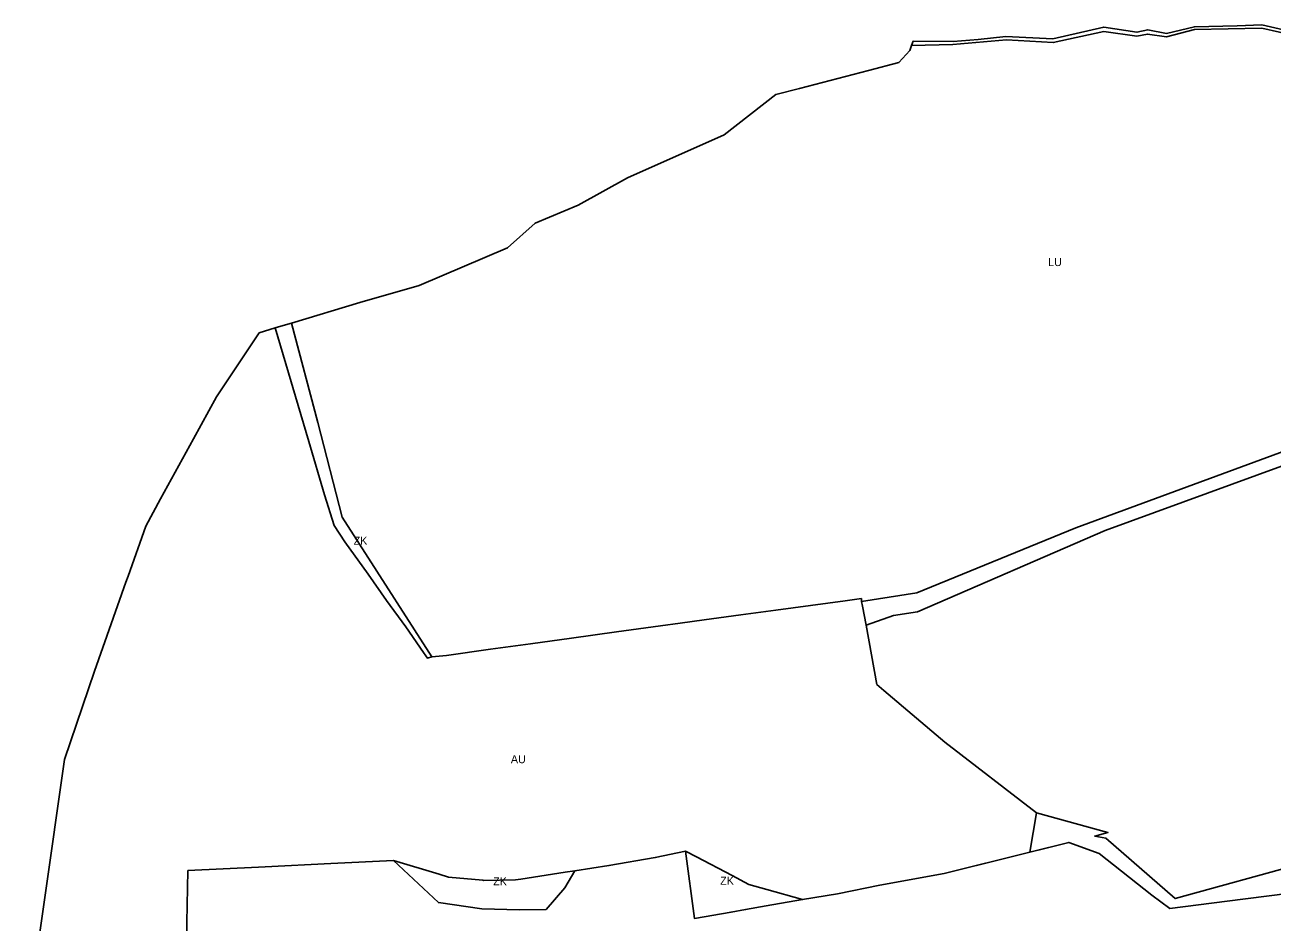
# Model space of a CAD drawing. Extents: x -521261 to -517465, y -1182764 to -1179456.
# Drawn here: x -521236 to -520457, y -1180873 to -1180313 of the extents above; entities that cross this region are included whole.
import ezdxf

# ---------------------------------------------------------------- set-up
doc = ezdxf.new("R2010")
doc.units = 0
for name, color, linetype in [('90640013', 7, 'Continuous'), ('90710013', 7, 'Continuous'), ('90750013', 7, 'Continuous'), ('90770013', 7, 'Continuous')]:
    doc.layers.add(name, color=color, linetype=linetype)

msp = doc.modelspace()

# ---------------------------------------------------------------- linework, layer by layer
at = {"layer": '90640013'}
msp.add_lwpolyline([(-520430.53, -1180322.01), (-520463.59, -1180314.64), (-520505.71, -1180315.43), (-520523.12, -1180320.04), (-520535.11, -1180318.28), (-520541.7, -1180319.56), (-520562.36, -1180316.64), (-520593.96, -1180323.61), (-520623.24, -1180321.76), (-520656.71, -1180324.81), (-520682.5, -1180325.44), (-520681.46, -1180322.66), (-520656.46, -1180322.89), (-520640.91, -1180321.65), (-520623.67, -1180319.82), (-520594.16, -1180321.19), (-520562.44, -1180313.88), (-520541.65, -1180317.16), (-520534.97, -1180315.56), (-520523.11, -1180317.8), (-520505.74, -1180313.71), (-520478.98, -1180313.03), (-520463.57, -1180312.56), (-520429.19, -1180320.47)], dxfattribs=at)
at = {"layer": '90710013'}
for points in [[(-520982.12, -1180707.29), (-520984.95, -1180708.02), (-520985.98, -1180706.63), (-520987.41, -1180704.59), (-520998.52, -1180688.54), (-521010.53, -1180672.06), (-521022.04, -1180655.73), (-521036.66, -1180635.53), (-521043.32, -1180625.33), (-521049.31, -1180606.17), (-521059.04, -1180572.8), (-521080, -1180501.82), (-521076.54, -1180500.79), (-521069.84, -1180498.79), (-521053.35, -1180560.82), (-521038.23, -1180619.96), (-521027.44, -1180636.91)], [(-520772.933, -1180852.547), (-520750.61, -1180858.87), (-520773.26, -1180862.77), (-520786.22, -1180865.2), (-520795.24, -1180866.73), (-520818.13, -1180870.65), (-520823.65, -1180828.61), (-520816.859, -1180832.176), (-520794.487, -1180843.925), (-520784.08, -1180849.39)], [(-520898.888, -1180841.868), (-520892.8, -1180840.93), (-520899.15, -1180851.67), (-520910.87, -1180865.15), (-520927.48, -1180865.42), (-520950.88, -1180864.7), (-520978.13, -1180860.76), (-521006.09, -1180834.57), (-520977.554, -1180843.132), (-520971.86, -1180844.84), (-520950.267, -1180846.845), (-520949.78, -1180846.89), (-520929.98, -1180846.66), (-520926.691, -1180846.153)]]:
    msp.add_lwpolyline(points, close=True, dxfattribs=at)
for points in [[(-520418.21, -1180576.2), (-520561.44, -1180628.41), (-520678.77, -1180679.14), (-520693.72, -1180681.5), (-520710.85, -1180687.4), (-520713.2, -1180675.69), (-520713.69, -1180672.62), (-520679.15, -1180667.26), (-520579.89, -1180626.79), (-520418.64, -1180567.25)], [(-520447.63, -1180855.08), (-520485.24, -1180860), (-520521.14, -1180864.38), (-520532.28, -1180856.24), (-520565.24, -1180830.11), (-520584.27, -1180823.22), (-520608.5, -1180829.229), (-520604.38, -1180804.7), (-520559.81, -1180816.94), (-520567.99, -1180819.26), (-520561.06, -1180820.59), (-520517.73, -1180858.28), (-520437.72, -1180836.09)]]:
    msp.add_lwpolyline(points, dxfattribs=at)
at = {"layer": '90750013'}
msp.add_lwpolyline([(-521236.44, -1180945.21), (-521211.68, -1180771.41), (-521193.04, -1180716.3), (-521173.37, -1180660.62), (-521171.97, -1180656.94), (-521160.99, -1180625.55), (-521151.7, -1180608.67), (-521131.22, -1180571.13), (-521116.74, -1180544.81), (-521090.08, -1180504.84), (-521080, -1180501.82), (-521059.04, -1180572.8), (-521049.31, -1180606.17), (-521043.32, -1180625.33), (-521036.66, -1180635.53), (-521022.04, -1180655.73), (-521010.53, -1180672.06), (-520998.52, -1180688.54), (-520987.41, -1180704.59), (-520985.98, -1180706.63), (-520984.95, -1180708.02), (-520982.12, -1180707.29), (-520972.99, -1180706.39), (-520945.52, -1180702.45), (-520920.54, -1180699.08), (-520894.99, -1180695.67), (-520866.85, -1180691.76), (-520839.32, -1180687.91), (-520826.97, -1180686.18), (-520811.97, -1180684.15), (-520789.12, -1180681.02), (-520767.28, -1180678.06), (-520745.61, -1180675.16), (-520724.02, -1180672.26), (-520713.87, -1180670.87), (-520713.69, -1180672.62), (-520713.2, -1180675.69), (-520710.85, -1180687.4), (-520704.09, -1180724.52), (-520699.81, -1180728.35), (-520661.61, -1180760.58), (-520604.38, -1180804.7), (-520608.5, -1180829.229), (-520662.13, -1180842.53), (-520702.34, -1180849.97), (-520728.86, -1180855.3), (-520750.61, -1180858.87), (-520772.933, -1180852.547), (-520784.08, -1180849.39), (-520794.487, -1180843.925), (-520816.859, -1180832.176), (-520823.65, -1180828.61), (-520842.59, -1180832.65), (-520871.59, -1180837.65), (-520892.8, -1180840.93), (-520898.888, -1180841.868), (-520926.691, -1180846.153), (-520929.98, -1180846.66), (-520949.78, -1180846.89), (-520950.267, -1180846.845), (-520971.86, -1180844.84), (-520977.554, -1180843.132), (-521006.09, -1180834.57), (-521045.3, -1180836.39), (-521086.39, -1180838.41), (-521090.43, -1180838.7), (-521134.59, -1180840.77), (-521135.49, -1180884)], dxfattribs=at)
at = {"layer": '90770013'}
for points in [[(-520418.64, -1180567.25), (-520579.89, -1180626.79), (-520679.15, -1180667.26), (-520713.69, -1180672.62), (-520713.87, -1180670.87), (-520724.02, -1180672.26), (-520745.61, -1180675.16), (-520767.28, -1180678.06), (-520789.12, -1180681.02), (-520811.97, -1180684.15), (-520826.97, -1180686.18), (-520839.32, -1180687.91), (-520866.85, -1180691.76), (-520894.99, -1180695.67), (-520920.54, -1180699.08), (-520945.52, -1180702.45), (-520972.99, -1180706.39), (-520982.12, -1180707.29), (-521027.44, -1180636.91), (-521038.23, -1180619.96), (-521053.35, -1180560.82), (-521069.84, -1180498.79), (-521027.14, -1180486), (-520990.12, -1180475.22), (-520934.86, -1180451.88), (-520917.68, -1180436.32), (-520890.7, -1180425.05), (-520859.95, -1180408.13), (-520799.56, -1180381.23), (-520767.33, -1180356.04), (-520752.44, -1180352.25), (-520709.38, -1180341.01), (-520690.43, -1180335.96), (-520683.47, -1180328.57), (-520682.5, -1180325.44), (-520656.71, -1180324.81), (-520623.24, -1180321.76), (-520593.96, -1180323.61), (-520562.36, -1180316.64), (-520541.7, -1180319.56), (-520535.11, -1180318.28), (-520523.12, -1180320.04), (-520505.71, -1180315.43), (-520463.59, -1180314.64), (-520430.53, -1180322.01)], [(-520437.72, -1180836.09), (-520517.73, -1180858.28), (-520561.06, -1180820.59), (-520567.99, -1180819.26), (-520559.81, -1180816.94), (-520604.38, -1180804.7), (-520661.61, -1180760.58), (-520699.81, -1180728.35), (-520704.09, -1180724.52), (-520710.85, -1180687.4), (-520693.72, -1180681.5), (-520678.77, -1180679.14), (-520561.44, -1180628.41), (-520418.21, -1180576.2)], [(-521135.49, -1180884), (-521134.59, -1180840.77), (-521090.43, -1180838.7), (-521086.39, -1180838.41), (-521045.3, -1180836.39), (-521006.09, -1180834.57), (-520978.13, -1180860.76), (-520950.88, -1180864.7), (-520927.48, -1180865.42), (-520910.87, -1180865.15), (-520899.15, -1180851.67), (-520892.8, -1180840.93), (-520871.59, -1180837.65), (-520842.59, -1180832.65), (-520823.65, -1180828.61), (-520818.13, -1180870.65), (-520795.24, -1180866.73), (-520786.22, -1180865.2), (-520773.26, -1180862.77), (-520750.61, -1180858.87), (-520728.86, -1180855.3), (-520702.34, -1180849.97), (-520662.13, -1180842.53), (-520584.27, -1180823.22), (-520565.24, -1180830.11), (-520532.28, -1180856.24), (-520521.14, -1180864.38), (-520485.24, -1180860), (-520447.63, -1180855.08)]]:
    msp.add_lwpolyline(points, dxfattribs=at)

# ---------------------------------------------------------------- texts
at = {"layer": '90710013'}
for rotation, p in [(360, (-521031.06, -1180637.245)), (0, (-520943.891, -1180849.995)), (0, (-520802.061, -1180849.63))]:
    msp.add_text('ZK', height=5, rotation=rotation, dxfattribs=at).set_placement(p)
at = {"layer": '90750013'}
msp.add_text('AU', height=5, rotation=360, dxfattribs=at).set_placement((-520932.83, -1180773.716))
at = {"layer": '90770013'}
msp.add_text('LU', height=5, rotation=360, dxfattribs=at).set_placement((-520597.153, -1180463.185))

doc.saveas('drawing.dxf')
